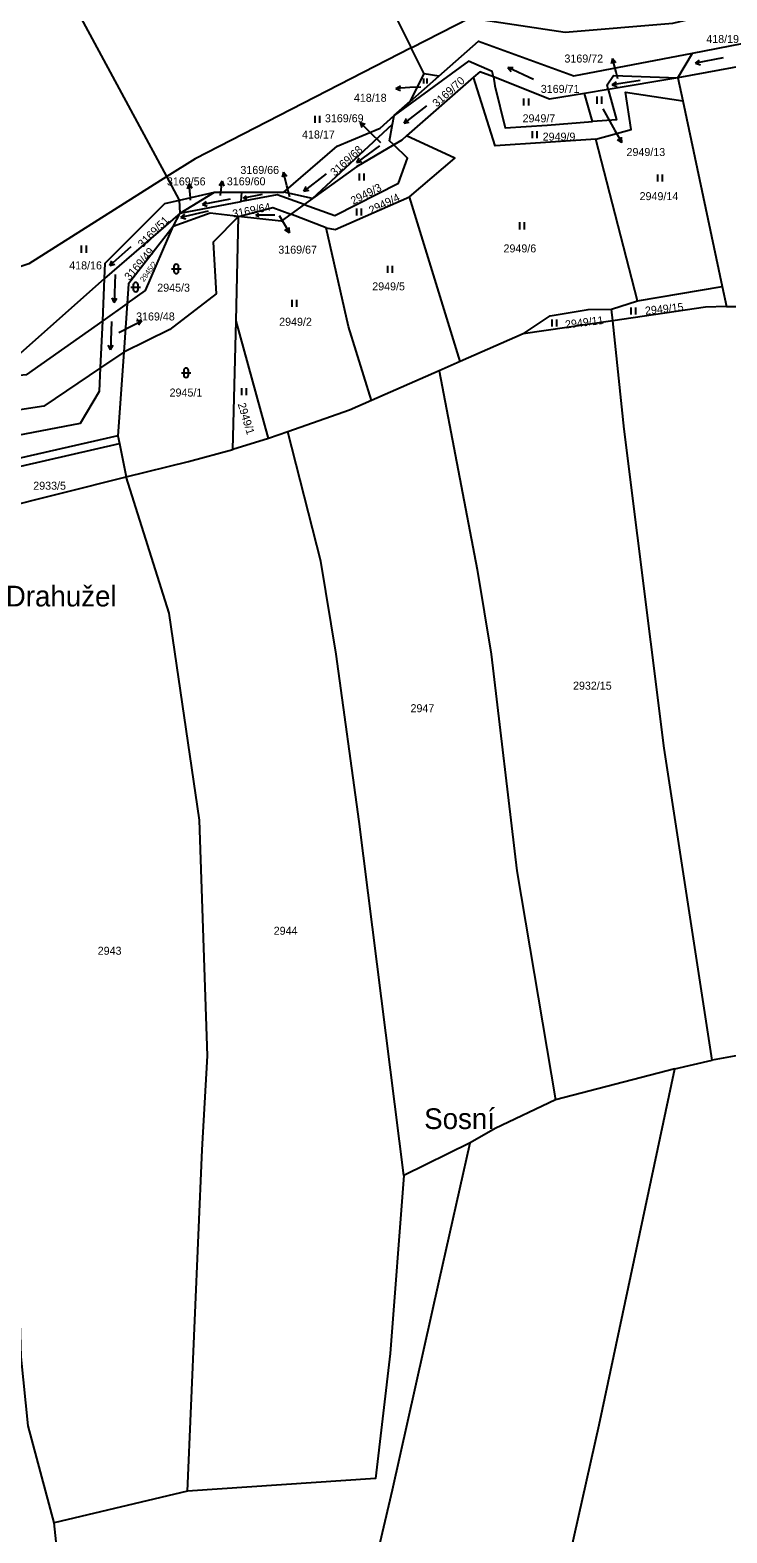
# Model space of a CAD drawing. Extents: x -755528 to -748832, y -1118122 to -1111095.
# Drawn here: x -754093.6 to -753945.5, y -1114095.9 to -1113776.6 of the extents above; entities that cross this region are included whole.
import ezdxf

# ---------------------------------------------------------------- set-up
doc = ezdxf.new("R2010")
doc.units = 0
for name, color, linetype in [('DZ_DO_PUPFL', 7, 'Continuous'), ('DZ_NAD_ZPF', 7, 'Continuous'), ('legenda barvy', 7, 'Continuous'), ('TZ_UMVŽST', 7, 'Continuous')]:
    doc.layers.add(name, color=color, linetype=linetype)

msp = doc.modelspace()

# ---------------------------------------------------------------- linework, layer by layer
at = {"layer": 'DZ_NAD_ZPF'}
for p, q in [((-753952.86, -1113781.5), (-753942.3, -1113779.47)), ((-754009.89, -1113785.86), (-754012.65, -1113780.4)), ((-753955.98, -1113786.77), (-753952.86, -1113781.5)), ((-754012.87, -1113791.76), (-754009.89, -1113785.86)), ((-754006.76, -1113786.36), (-754009.89, -1113785.86)), ((-753937.76, -1113783.38), (-753955.98, -1113786.77)), ((-753999.38, -1113786.6), (-754013.62, -1113799.06)), ((-754012.87, -1113791.76), (-754006.76, -1113786.36)), ((-753970.77, -1113789.22), (-753975.82, -1113790.05)), ((-753955.98, -1113786.77), (-753970.77, -1113789.22)), ((-753955.98, -1113786.77), (-753954.94, -1113791.66)), ((-754016.24, -1113794.73), (-754012.87, -1113791.76)), ((-753974.1, -1113796.03), (-753975.82, -1113790.05)), ((-753954.94, -1113791.66), (-753946.54, -1113831.06)), ((-754016.64, -1113796.59), (-754016.24, -1113794.73)), ((-754033.63, -1113812.39), (-754016.64, -1113796.59)), ((-753964.58, -1113834.1), (-753973.43, -1113799.79)), ((-754061.88, -1113812.74), (-754064.58, -1113807.73)), ((-754061.88, -1113812.74), (-754054.48, -1113811.04)), ((-754061.74, -1113815.5), (-754054.48, -1113811.04)), ((-754054.48, -1113811.04), (-754048.64, -1113811.05)), ((-754048.78, -1113813.04), (-754048.64, -1113811.05)), ((-754048.64, -1113811.05), (-754039.7, -1113811.06)), ((-754033.63, -1113812.39), (-754039.7, -1113811.06)), ((-754061.74, -1113815.5), (-754061.88, -1113812.74)), ((-754061.74, -1113815.5), (-754048.78, -1113813.04)), ((-754035.38, -1113813.65), (-754038.25, -1113815.72)), ((-754033.63, -1113812.39), (-754035.38, -1113813.65)), ((-754002.27, -1113847.04), (-754013.01, -1113811.99)), ((-754061.74, -1113815.5), (-754077.8, -1113829.36)), ((-754063.25, -1113818.31), (-754061.74, -1113815.5)), ((-754049.88, -1113838.39), (-754049.35, -1113816.17)), ((-754030.73, -1113818.62), (-754038.25, -1113815.72)), ((-754077.8, -1113829.36), (-754097, -1113846.43)), ((-754078.21, -1113838.35), (-754077.8, -1113829.36)), ((-753970.05, -1113835.87), (-753964.58, -1113834.1)), ((-753964.58, -1113834.1), (-753946.54, -1113831.06)), ((-753946.54, -1113831.06), (-753945.62, -1113835.35)), ((-754073.03, -1113834.68), (-754078.21, -1113838.35)), ((-754073.03, -1113834.68), (-754073.74, -1113845.05)), ((-753969.79, -1113838.34), (-753970.05, -1113835.87)), ((-754078.67, -1113848.38), (-754078.21, -1113838.35)), ((-754050.53, -1113865.73), (-754049.88, -1113838.39)), ((-754043, -1113863.39), (-754049.88, -1113838.39)), ((-753969.79, -1113838.34), (-753988.88, -1113841.15)), ((-753988.88, -1113841.15), (-754002.27, -1113847.04)), ((-754073.74, -1113845.05), (-754078.67, -1113848.38)), ((-754073.74, -1113845.05), (-754074.96, -1113862.77)), ((-754006.71, -1113848.99), (-754021.06, -1113855.3)), ((-754002.27, -1113847.04), (-754006.71, -1113848.99)), ((-754074.96, -1113862.77), (-754074.63, -1113864.42)), ((-754038.9, -1113861.96), (-754043, -1113863.39)), ((-754107.55, -1113872.02), (-754074.63, -1113864.42)), ((-754074.63, -1113864.42), (-754073.23, -1113871.5)), ((-754043, -1113863.39), (-754050.53, -1113865.73)), ((-754105.53, -1113879.61), (-754073.23, -1113871.5)), ((-753956.63, -1113997.27), (-753948.67, -1113995.43)), ((-753956.63, -1113997.27), (-753981.96, -1114003.88)), ((-754000.1, -1114013.04), (-754014.24, -1114019.94)), ((-754060.18, -1114086.99), (-754088.55, -1114093.73)), ((-754087.11, -1114106.92), (-754088.55, -1114093.73))]:
    msp.add_line(p, q, dxfattribs=at)
for points in [[(-754122.19, -1113573.44), (-754070.59, -1113671.33), (-754032.26, -1113741.04), (-754012.65, -1113780.4)], [(-754064.58, -1113807.73), (-754088.01, -1113764.21), (-754117.58, -1113708.88), (-754162, -1113623.09)], [(-754012.65, -1113780.4), (-754000.2, -1113774.02), (-753979.95, -1113777.07), (-753957.06, -1113775.16), (-753936.3, -1113770.26), (-753901.25, -1113770.28)], [(-754006.76, -1113786.36), (-753998.37, -1113778.95), (-753978.1, -1113786.34), (-753952.86, -1113781.5)], [(-754012.65, -1113780.4), (-754058.54, -1113803.92), (-754064.58, -1113807.73)], [(-753995.19, -1113786.56), (-753995.42, -1113785.38), (-754000.46, -1113783.17), (-754016.24, -1113794.73)], [(-753995.19, -1113786.56), (-753998.04, -1113785.43), (-753999.38, -1113786.6)], [(-753970.77, -1113789.22), (-753971.03, -1113788.22), (-753969.67, -1113786.24), (-753955.98, -1113786.77)], [(-753973.43, -1113799.79), (-753994.81, -1113801.19), (-753999.38, -1113786.6)], [(-753975.82, -1113790.05), (-753983.25, -1113791.28), (-753995.19, -1113786.56)], [(-753995.19, -1113786.56), (-753994.88, -1113788.41), (-753992.68, -1113797.36), (-753983.78, -1113796.83), (-753974.1, -1113796.03)], [(-753970.77, -1113789.22), (-753969, -1113795.66), (-753974.1, -1113796.03)], [(-753973.43, -1113799.79), (-753965.87, -1113797.7), (-753967.09, -1113789.75), (-753954.94, -1113791.66)], [(-754039.7, -1113811.06), (-754028.38, -1113801.26), (-754019.26, -1113797.4), (-754016.24, -1113794.73)], [(-754016.36, -1113800.98), (-754017.29, -1113800.1), (-754016.64, -1113796.59)], [(-754035.38, -1113813.65), (-754028.87, -1113815.99), (-754015.34, -1113809.11), (-754013.42, -1113803.79), (-754016.36, -1113800.98)], [(-754016.36, -1113800.98), (-754024.26, -1113805.65), (-754033.63, -1113812.39)], [(-754013.62, -1113799.06), (-754014.67, -1113799.98), (-754016.36, -1113800.98)], [(-754013.01, -1113811.99), (-754003.39, -1113803.84), (-754013.62, -1113799.06)], [(-754064.58, -1113807.73), (-754093.92, -1113826.24), (-754104.86, -1113829.84)], [(-754035.38, -1113813.65), (-754041.13, -1113811.59), (-754048.78, -1113813.04)], [(-754077.8, -1113829.36), (-754077.65, -1113826.13), (-754064.98, -1113813.46), (-754061.88, -1113812.74)], [(-754049.35, -1113816.17), (-754042.04, -1113814.26), (-754038.25, -1113815.72)], [(-754030.73, -1113818.62), (-754028.8, -1113818.98), (-754013.01, -1113811.99)], [(-754049.35, -1113816.17), (-754054.73, -1113821.68), (-754054.12, -1113832.64), (-754063.97, -1113840.21), (-754073.74, -1113845.05)], [(-754049.35, -1113816.17), (-754055.37, -1113815.51), (-754063.25, -1113818.31)], [(-754038.25, -1113815.72), (-754040.31, -1113817.2), (-754049.35, -1113816.17)], [(-754063.25, -1113818.31), (-754072.74, -1113830.54), (-754073.03, -1113834.68)], [(-754073.03, -1113834.68), (-754069.12, -1113831.92), (-754063.25, -1113818.31)], [(-754021.06, -1113855.3), (-754025.97, -1113839.6), (-754030.73, -1113818.62)], [(-753988.88, -1113841.15), (-753983.15, -1113837.33), (-753975.02, -1113835.97), (-753970.05, -1113835.87)], [(-753945.62, -1113835.35), (-753950.08, -1113835.43), (-753969.79, -1113838.34)], [(-753945.62, -1113835.35), (-753937.19, -1113835.32), (-753933.88, -1113834.39)], [(-754078.21, -1113838.35), (-754094.44, -1113849.84), (-754135.16, -1113853.97)], [(-753948.67, -1113995.43), (-753958.86, -1113929.16), (-753967.37, -1113861.41), (-753969.79, -1113838.34)], [(-754078.67, -1113848.38), (-754090.72, -1113856.52), (-754127.21, -1113862.08), (-754156.31, -1113858.73), (-754163.7, -1113858.09), (-754194.79, -1113857.45), (-754206.68, -1113870.75), (-754200.79, -1113882.1)], [(-754196.38, -1113886.18), (-754176.31, -1113877.74), (-754148.04, -1113874.54), (-754118.15, -1113866.87), (-754082.91, -1113860.1), (-754078.89, -1113853.29), (-754078.67, -1113848.38)], [(-754006.71, -1113848.99), (-753998.6, -1113891.2), (-753995.68, -1113909.16), (-753990.2, -1113955.19), (-753981.96, -1114003.88)], [(-754021.06, -1113855.3), (-754025.74, -1113857.36), (-754038.9, -1113861.96)], [(-754074.96, -1113862.77), (-754109.23, -1113870.62), (-754145.05, -1113879.1), (-754168.15, -1113885.85), (-754182.95, -1113885.07)], [(-754014.24, -1114019.94), (-754023.68, -1113944.71), (-754028.59, -1113909.16), (-754031.86, -1113889.4), (-754038.9, -1113861.96)], [(-754073.23, -1113871.5), (-754060.01, -1113868.27), (-754050.53, -1113865.73)], [(-754060.18, -1114086.99), (-754057.07, -1114014.48), (-754055.97, -1113994.54), (-754057.62, -1113944.46), (-754064.09, -1113900.48), (-754073.23, -1113871.5)], [(-753915.44, -1113988.98), (-753930, -1113992.06), (-753948.67, -1113995.43)], [(-753999.34, -1114191.23), (-753983.34, -1114120.28), (-753972.68, -1114072.95), (-753956.63, -1113997.27)], [(-753981.96, -1114003.88), (-753994.84, -1114009.94), (-754000.1, -1114013.04)], [(-754035.66, -1114168.37), (-754030.23, -1114144.78), (-754016.63, -1114086.74), (-754006.74, -1114042.3), (-754000.1, -1114013.04)], [(-754014.24, -1114019.94), (-754017.12, -1114057.76), (-754020.2, -1114084.31), (-754060.18, -1114086.99)], [(-754088.55, -1114093.73), (-754094.06, -1114073.15), (-754095.57, -1114058.45), (-754096.25, -1114034.06)]]:
    msp.add_lwpolyline(points, dxfattribs=at)
at = {"layer": 'legenda barvy'}
for p, q in [((-753969.897, -1113782.641), (-753970.121, -1113783.738)), ((-753969.12, -1113785.54), (-753969.897, -1113782.641)), ((-753969.897, -1113782.641), (-753969.154, -1113783.479)), ((-753968.73, -1113786.98), (-753969.12, -1113785.54)), ((-754015.927, -1113788.977), (-754014.953, -1113788.425)), ((-754012.93, -1113788.82), (-754015.927, -1113788.977)), ((-754015.927, -1113788.977), (-754014.901, -1113789.425)), ((-754010.59, -1113788.7), (-754012.93, -1113788.82)), ((-753971.95, -1113793.34), (-753969.37, -1113797.9)), ((-754021.34, -1113798.35), (-754023.462, -1113796.228)), ((-754023.462, -1113796.228), (-754022.4, -1113796.582)), ((-754023.462, -1113796.228), (-754023.108, -1113797.29)), ((-754019.09, -1113800.57), (-754021.34, -1113798.35)), ((-753969.37, -1113797.9), (-753967.87, -1113800.499)), ((-753967.87, -1113800.499), (-753968.804, -1113799.882)), ((-753967.87, -1113800.499), (-753967.937, -1113799.381)), ((-754039.796, -1113806.768), (-754040.04, -1113807.861)), ((-754039.07, -1113809.68), (-754039.796, -1113806.768)), ((-754039.796, -1113806.768), (-754039.068, -1113807.619)), ((-754059.832, -1113809.25), (-754060.243, -1113810.292)), ((-754059.57, -1113812.24), (-754059.832, -1113809.25)), ((-754059.832, -1113809.25), (-754059.245, -1113810.204)), ((-754052.814, -1113808.721), (-754053.433, -1113809.654)), ((-754053.19, -1113811.77), (-754053.18, -1113811.7)), ((-754053.18, -1113811.7), (-754052.814, -1113808.721)), ((-754052.814, -1113808.721), (-754052.439, -1113809.776)), ((-754038.47, -1113812), (-754039.07, -1113809.68)), ((-754059.53, -1113812.72), (-754059.57, -1113812.24)), ((-754040.72, -1113815.99), (-754040.07, -1113817.08)), ((-754040.07, -1113817.08), (-754038.524, -1113819.652)), ((-754038.524, -1113819.652), (-754039.469, -1113819.052)), ((-754038.524, -1113819.652), (-754038.611, -1113818.536)), ((-754074.81, -1113840.87), (-754072.59, -1113839.73)), ((-754072.59, -1113839.73), (-754069.916, -1113838.368)), ((-754069.916, -1113838.368), (-754071.036, -1113838.376)), ((-754069.916, -1113838.368), (-754070.581, -1113839.268))]:
    msp.add_line(p, q, dxfattribs=at)
at = {"layer": 'TZ_UMVŽST'}
for p, q in [((-753946.334, -1113782.502), (-753952.223, -1113783.647)), ((-753952.223, -1113783.647), (-753951.36, -1113782.969)), ((-753992.101, -1113784.557), (-753991.003, -1113784.516)), ((-753986.663, -1113787.093), (-753992.101, -1113784.557)), ((-753992.101, -1113784.557), (-753991.427, -1113785.425)), ((-753952.223, -1113783.647), (-753951.168, -1113783.953)), ((-754009.942, -1113787.92), (-754009.942, -1113786.915)), ((-754009.272, -1113787.92), (-754009.272, -1113786.915)), ((-753963.985, -1113787.285), (-753969.911, -1113788.224)), ((-753969.911, -1113788.224), (-753969.025, -1113787.575)), ((-753969.911, -1113788.224), (-753968.868, -1113788.566)), ((-753988.681, -1113792.62), (-753988.681, -1113791.12)), ((-753987.68, -1113792.62), (-753987.68, -1113791.12)), ((-753973.161, -1113792.24), (-753973.161, -1113790.74)), ((-753972.16, -1113792.24), (-753972.16, -1113790.74)), ((-754033.041, -1113796.31), (-754033.041, -1113794.81)), ((-754032.04, -1113796.31), (-754032.04, -1113794.81)), ((-754009.415, -1113792.687), (-754014.143, -1113796.381)), ((-754014.143, -1113796.381), (-754013.682, -1113795.384)), ((-754014.143, -1113796.381), (-754013.064, -1113796.174)), ((-753986.861, -1113799.55), (-753986.861, -1113798.05)), ((-753985.86, -1113799.55), (-753985.86, -1113798.05)), ((-754019.382, -1113801.18), (-754024.236, -1113804.706)), ((-754024.236, -1113804.706), (-754023.74, -1113803.726)), ((-754024.236, -1113804.706), (-754023.151, -1113804.538)), ((-754030.705, -1113807.107), (-754035.433, -1113810.801)), ((-754023.641, -1113808.58), (-754023.641, -1113807.08)), ((-754022.64, -1113808.58), (-754022.64, -1113807.08)), ((-753960.241, -1113808.75), (-753960.241, -1113807.25)), ((-753959.24, -1113808.75), (-753959.24, -1113807.25)), ((-754044.309, -1113811.533), (-754048.255, -1113812.3)), ((-754035.433, -1113810.801), (-754034.972, -1113809.804)), ((-754035.433, -1113810.801), (-754034.354, -1113810.594)), ((-754051.144, -1113812.532), (-754057.033, -1113813.677)), ((-754057.033, -1113813.677), (-754056.17, -1113812.999)), ((-754057.033, -1113813.677), (-754055.978, -1113813.983)), ((-754048.255, -1113812.3), (-754047.677, -1113811.845)), ((-754048.255, -1113812.3), (-754047.549, -1113812.505)), ((-754024.211, -1113815.97), (-754024.211, -1113814.47)), ((-754023.21, -1113815.97), (-754023.21, -1113814.47)), ((-754055.776, -1113815.091), (-754061.622, -1113816.44)), ((-754061.622, -1113816.44), (-754060.782, -1113815.732)), ((-754061.622, -1113816.44), (-754060.557, -1113816.709)), ((-754045.671, -1113815.884), (-754045.017, -1113815.548)), ((-754041.651, -1113815.884), (-754045.671, -1113815.884)), ((-754045.671, -1113815.884), (-754045.017, -1113816.22)), ((-753989.591, -1113818.93), (-753989.591, -1113817.43)), ((-753988.59, -1113818.93), (-753988.59, -1113817.43)), ((-754082.681, -1113823.89), (-754082.681, -1113822.39)), ((-754081.68, -1113823.89), (-754081.68, -1113822.39)), ((-754072.199, -1113822.628), (-754076.658, -1113826.642)), ((-754076.658, -1113826.642), (-754076.267, -1113825.616)), ((-754076.658, -1113826.642), (-754075.596, -1113826.361)), ((-754063.571, -1113827.341), (-754061.569, -1113827.341)), ((-754063.071, -1113826.841), (-754063.071, -1113827.842)), ((-754062.069, -1113827.842), (-754062.069, -1113826.841)), ((-754017.601, -1113828.2), (-754017.601, -1113826.7)), ((-754016.6, -1113828.2), (-754016.6, -1113826.7)), ((-754075.554, -1113828.509), (-754075.764, -1113834.505)), ((-754071.701, -1113830.701), (-754071.701, -1113831.702)), ((-754070.699, -1113831.702), (-754070.699, -1113830.701)), ((-754075.764, -1113834.505), (-754076.231, -1113833.511)), ((-754075.764, -1113834.505), (-754075.229, -1113833.546)), ((-754072.201, -1113831.201), (-754070.199, -1113831.201)), ((-754037.921, -1113835.42), (-754037.921, -1113833.92)), ((-754036.92, -1113835.42), (-754036.92, -1113833.92)), ((-753965.921, -1113837), (-753965.921, -1113835.5)), ((-753964.92, -1113837), (-753964.92, -1113835.5)), ((-754076.344, -1113838.529), (-754076.554, -1113844.525)), ((-753982.691, -1113839.57), (-753982.691, -1113838.07)), ((-753981.69, -1113839.57), (-753981.69, -1113838.07)), ((-754076.554, -1113844.525), (-754077.021, -1113843.531)), ((-754076.554, -1113844.525), (-754076.019, -1113843.566)), ((-754061.481, -1113849.391), (-754059.479, -1113849.391)), ((-754060.981, -1113848.891), (-754060.981, -1113849.892)), ((-754059.979, -1113849.892), (-754059.979, -1113848.891)), ((-754048.671, -1113854.19), (-754048.671, -1113852.69)), ((-754047.67, -1113854.19), (-754047.67, -1113852.69))]:
    msp.add_line(p, q, dxfattribs=at)
for centre, start, end in [((-754062.57, -1113826.8409), 0, 180), ((-754071.2, -1113830.7009), 0, 180), ((-754062.57, -1113827.8409), 180, 359.987886), ((-754071.2, -1113831.7009), 180, 359.987886), ((-754060.48, -1113848.8909), 0, 180), ((-754060.48, -1113849.8909), 180, 359.987886)]:
    msp.add_arc(centre, 0.5, start, end, dxfattribs=at)

# ---------------------------------------------------------------- texts
at = {"layer": 'DZ_DO_PUPFL'}
for s, p in [('418/19', (-753949.94, -1113779.34)), ('3169/72', (-753980.083, -1113783.49)), ('3169/71', (-753985.11, -1113789.94)), ('418/18', (-754024.825, -1113791.828)), ('3169/69', (-754030.983, -1113796.18)), ('2949/7', (-753988.98, -1113796.19)), ('418/17', (-754035.84, -1113799.63)), ('2949/9', (-753984.71, -1113800.08)), ('2949/13', (-753966.89, -1113803.358)), ('3169/66', (-754048.943, -1113807.16)), ('3169/56', (-754064.563, -1113809.6)), ('3169/60', (-754051.83, -1113809.57)), ('2949/14', (-753964.11, -1113812.73)), ('3169/67', (-754040.89, -1113824.098)), ('2949/6', (-753993.03, -1113823.83)), ('418/16', (-754085.32, -1113827.44)), ('2945/3', (-754066.62, -1113832.17)), ('2949/5', (-754020.93, -1113831.89)), ('3169/48', (-754071.11, -1113838.29)), ('2949/2', (-754040.71, -1113839.41)), ('2945/1', (-754063.99, -1113854.45)), ('2933/5', (-754092.97, -1113874.25)), ('2932/15', (-753978.26, -1113916.73)), ('2947', (-754012.79, -1113921.52)), ('2944', (-754041.87, -1113968.8)), ('2943', (-754079.27, -1113973.05))]:
    msp.add_text(s, height=1.7, dxfattribs=at).set_placement(p)
for s, height, rotation, p in [('3169/70', 1.7, 42, (-754007.201, -1113793.071)), ('3169/68', 1.7, 42, (-754028.911, -1113807.741)), ('2949/3', 1.7, 27, (-754024.974, -1113813.747)), ('2949/4', 1.7, 26, (-754021.137, -1113815.763)), ('3169/64', 1.7, 10.999997, (-754050.477, -1113816.484)), ('3169/51', 1.7, 45, (-754069.738, -1113822.961)), ('3169/49', 1.7, 49, (-754072.498, -1113829.917)), ('2945/2', 1.14, 54, (-754069.464, -1113830.186)), ('2949/15', 1.7, 6, (-753962.871, -1113837.075)), ('2949/11', 1.7, 7, (-753979.836, -1113840.013)), ('2949/1', 1.7, 287, (-754049.542, -1113856.058))]:
    msp.add_text(s, height=height, rotation=rotation, dxfattribs=at).set_placement(p)
at = {"layer": 'legenda barvy'}
for s, p in [('Drahužel', (-754098.804, -1113899.05)), ('Sosní', (-754009.89, -1114010.08))]:
    msp.add_text(s, height=4.4, dxfattribs=at).set_placement(p)

doc.saveas('drawing.dxf')
